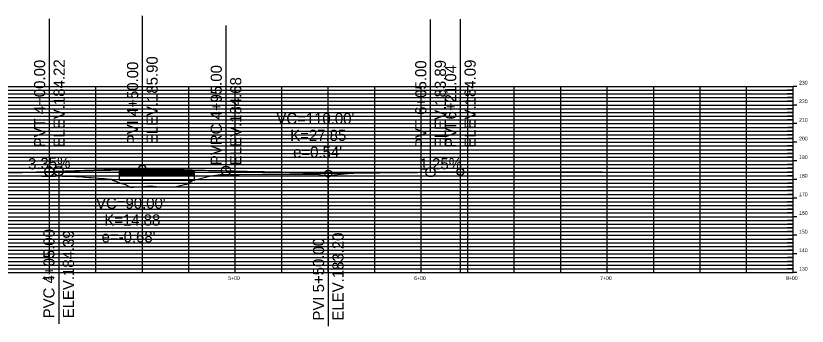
# Model space of a CAD drawing. Extents: x 1405440 to 1409538, y 1842123 to 1843178.
# Drawn here: x 1409112.2 to 1409537.8, y 1843011 to 1843177.7 of the extents above; entities that cross this region are included whole.
import ezdxf

# ---------------------------------------------------------------- set-up
doc = ezdxf.new("R2010")
doc.units = 0
for name, color, linetype in [('R_Axis_Annotation', 7, 'Continuous'), ('R_Exist Surface', 7, 'Continuous'), ('R_Grid Annot', 7, 'Continuous'), ('R_Grid_Minor', 7, 'Continuous'), ('R_SFHA', 7, 'Continuous'), ('R_Vert Alg', 7, 'Continuous'), ('R_Vert Alg Annot', 7, 'Continuous')]:
    doc.layers.add(name, color=color, linetype=linetype)

msp = doc.modelspace()

# ---------------------------------------------------------------- linework, layer by layer
for p, q in [((1408730.23, 1843139.81), (1409530.23, 1843139.81)), ((1408730.23, 1843139.81), (1409530.23, 1843139.81)), ((1409130.23, 1843039.81), (1409130.23, 1843139.81)), ((1409230.23, 1843039.81), (1409230.23, 1843139.81)), ((1409330.23, 1843039.81), (1409330.23, 1843139.81)), ((1409430.23, 1843039.81), (1409430.23, 1843139.81)), ((1409530.23, 1843039.81), (1409530.23, 1843139.81)), ((1408730.23, 1843129.81), (1409530.23, 1843129.81)), ((1408730.23, 1843119.81), (1409530.23, 1843119.81)), ((1408730.23, 1843109.81), (1409530.23, 1843109.81)), ((1408730.23, 1843099.81), (1409530.23, 1843099.81)), ((1408730.23, 1843089.81), (1409530.23, 1843089.81)), ((1408730.23, 1843079.81), (1409530.23, 1843079.81)), ((1408730.23, 1843069.81), (1409530.23, 1843069.81)), ((1408730.23, 1843059.81), (1409530.23, 1843059.81)), ((1408730.23, 1843049.81), (1409530.23, 1843049.81)), ((1408730.23, 1843039.81), (1409530.23, 1843039.81))]:
    msp.add_line(p, q)
at = {"layer": 'R_Exist Surface'}
msp.add_lwpolyline([(1409111.85, 1843091.83), (1409114.66, 1843091.79), (1409115.45, 1843091.79), (1409118.13, 1843091.79), (1409119.05, 1843091.77), (1409122.65, 1843091.69), (1409126.25, 1843091.6), (1409127.97, 1843091.55), (1409129.85, 1843091.57), (1409131.37, 1843091.59), (1409133.45, 1843091.63), (1409136.1, 1843091.69), (1409137.05, 1843091.66), (1409140.65, 1843091.53), (1409144.24, 1843091.38), (1409145.42, 1843091.32), (1409147.84, 1843091.15), (1409151.44, 1843090.89), (1409152.67, 1843090.79), (1409155.04, 1843090.63), (1409158.64, 1843090.36), (1409159.81, 1843090.27), (1409163.26, 1843089.98), (1409163.53, 1843089.95), (1409164.23, 1843089.35), (1409166.85, 1843088.47), (1409168.95, 1843087.72), (1409170.76, 1843087.29), (1409174.07, 1843085.42), (1409174.08, 1843085.42), (1409175.83, 1843085.66), (1409179.08, 1843085.83), (1409184.38, 1843086.36), (1409187.74, 1843086.06), (1409193.95, 1843085.83), (1409193.96, 1843085.83), (1409197.74, 1843085.9), (1409202.98, 1843087.13), (1409204.01, 1843087.28), (1409207.22, 1843089.28), (1409207.29, 1843089.3), (1409217.15, 1843091.7), (1409222.08, 1843092.46), (1409228.66, 1843092.53), (1409232.34, 1843092.52), (1409244.89, 1843092.6), (1409253.41, 1843092.58), (1409254.67, 1843092.59), (1409258.26, 1843092.61), (1409261.85, 1843092.63), (1409264.61, 1843092.66), (1409265.43, 1843092.66), (1409269.02, 1843092.67), (1409272.61, 1843092.68), (1409274.36, 1843092.69), (1409276.2, 1843092.39), (1409279.24, 1843091.92), (1409279.24, 1843091.92), (1409279.78, 1843091.96), (1409283.37, 1843092.28), (1409286.96, 1843092.61), (1409290.54, 1843092.95), (1409294.05, 1843093.29), (1409294.13, 1843093.29), (1409294.19, 1843093.29), (1409294.39, 1843093.3), (1409297.72, 1843093.36), (1409301.31, 1843093.43), (1409304.89, 1843093.5), (1409306.87, 1843093.54), (1409308.48, 1843093.56), (1409312.07, 1843093.58), (1409315.55, 1843093.61), (1409315.66, 1843093.61), (1409319.24, 1843093.64), (1409322.83, 1843093.67), (1409323.22, 1843093.67), (1409326.42, 1843093.7), (1409330.1, 1843093.74), (1409333.77, 1843093.78), (1409336.06, 1843093.8), (1409337.45, 1843093.81), (1409339.42, 1843093.83), (1409341.13, 1843093.84), (1409344.8, 1843093.87), (1409348.48, 1843093.89), (1409351.3, 1843093.91), (1409352.16, 1843093.91), (1409355.83, 1843093.91), (1409359.51, 1843093.91), (1409359.69, 1843093.91), (1409363.03, 1843093.91), (1409363.19, 1843093.91), (1409366.87, 1843093.91), (1409370.54, 1843093.9), (1409374.22, 1843093.9), (1409377.9, 1843093.89), (1409379.51, 1843093.89), (1409381.57, 1843093.89), (1409385.25, 1843093.89), (1409388.12, 1843093.89), (1409388.93, 1843093.89), (1409392.6, 1843093.88), (1409396.28, 1843093.88), (1409399.96, 1843093.87), (1409402.67, 1843093.87), (1409413.03, 1843093.86), (1409427.7, 1843093.83), (1409437.94, 1843093.82), (1409442.23, 1843093.83)], dxfattribs=at)
at = {"layer": 'R_Grid Annot'}
for p, q in [((1409532.23, 1843139.81), (1409530.23, 1843139.81)), ((1409532.23, 1843139.81), (1409530.23, 1843139.81)), ((1409530.23, 1843137.81), (1409527.23, 1843137.81)), ((1409530.23, 1843135.81), (1409527.23, 1843135.81)), ((1409530.23, 1843133.81), (1409527.23, 1843133.81)), ((1409530.23, 1843131.81), (1409527.23, 1843131.81)), ((1409530.23, 1843127.81), (1409527.23, 1843127.81)), ((1409530.23, 1843125.81), (1409527.23, 1843125.81)), ((1409532.23, 1843129.81), (1409530.23, 1843129.81)), ((1409530.23, 1843123.81), (1409527.23, 1843123.81)), ((1409530.23, 1843121.81), (1409527.23, 1843121.81)), ((1409530.23, 1843117.81), (1409527.23, 1843117.81)), ((1409532.23, 1843119.81), (1409530.23, 1843119.81)), ((1409530.23, 1843115.81), (1409527.23, 1843115.81)), ((1409530.23, 1843113.81), (1409527.23, 1843113.81)), ((1409530.23, 1843111.81), (1409527.23, 1843111.81)), ((1409532.23, 1843109.81), (1409530.23, 1843109.81)), ((1409530.23, 1843107.81), (1409527.23, 1843107.81)), ((1409530.23, 1843105.81), (1409527.23, 1843105.81)), ((1409530.23, 1843103.81), (1409527.23, 1843103.81)), ((1409530.23, 1843101.81), (1409527.23, 1843101.81)), ((1409530.23, 1843097.81), (1409527.23, 1843097.81)), ((1409532.23, 1843099.81), (1409530.23, 1843099.81)), ((1409530.23, 1843095.81), (1409527.23, 1843095.81)), ((1409530.23, 1843093.81), (1409527.23, 1843093.81)), ((1409530.23, 1843091.81), (1409527.23, 1843091.81)), ((1409530.23, 1843087.81), (1409527.23, 1843087.81)), ((1409532.23, 1843089.81), (1409530.23, 1843089.81)), ((1409530.23, 1843085.81), (1409527.23, 1843085.81)), ((1409530.23, 1843083.81), (1409527.23, 1843083.81)), ((1409530.23, 1843081.81), (1409527.23, 1843081.81)), ((1409532.23, 1843079.81), (1409530.23, 1843079.81)), ((1409530.23, 1843077.81), (1409527.23, 1843077.81)), ((1409530.23, 1843075.81), (1409527.23, 1843075.81)), ((1409530.23, 1843073.81), (1409527.23, 1843073.81)), ((1409530.23, 1843071.81), (1409527.23, 1843071.81)), ((1409530.23, 1843067.81), (1409527.23, 1843067.81)), ((1409532.23, 1843069.81), (1409530.23, 1843069.81)), ((1409530.23, 1843065.81), (1409527.23, 1843065.81)), ((1409530.23, 1843063.81), (1409527.23, 1843063.81)), ((1409530.23, 1843061.81), (1409527.23, 1843061.81)), ((1409530.23, 1843057.81), (1409527.23, 1843057.81)), ((1409532.23, 1843059.81), (1409530.23, 1843059.81)), ((1409530.23, 1843055.81), (1409527.23, 1843055.81)), ((1409530.23, 1843053.81), (1409527.23, 1843053.81)), ((1409530.23, 1843051.81), (1409527.23, 1843051.81)), ((1409532.23, 1843049.81), (1409530.23, 1843049.81)), ((1409530.23, 1843047.81), (1409527.23, 1843047.81)), ((1409530.23, 1843045.81), (1409527.23, 1843045.81)), ((1409530.23, 1843043.81), (1409527.23, 1843043.81)), ((1409530.23, 1843041.81), (1409527.23, 1843041.81)), ((1409532.23, 1843039.81), (1409530.23, 1843039.81))]:
    msp.add_line(p, q, dxfattribs=at)
at = {"layer": 'R_Grid_Minor'}
for p, q in [((1409155.23, 1843039.81), (1409155.23, 1843139.81)), ((1409180.23, 1843039.81), (1409180.23, 1843139.81)), ((1409205.23, 1843039.81), (1409205.23, 1843139.81)), ((1409255.23, 1843039.81), (1409255.23, 1843139.81)), ((1409280.23, 1843039.81), (1409280.23, 1843139.81)), ((1409305.23, 1843039.81), (1409305.23, 1843139.81)), ((1409355.23, 1843039.81), (1409355.23, 1843139.81)), ((1409380.23, 1843039.81), (1409380.23, 1843139.81)), ((1409405.23, 1843039.81), (1409405.23, 1843139.81)), ((1409455.23, 1843039.81), (1409455.23, 1843139.81)), ((1409480.23, 1843039.81), (1409480.23, 1843139.81)), ((1409505.23, 1843039.81), (1409505.23, 1843139.81)), ((1408730.23, 1843137.81), (1409530.23, 1843137.81)), ((1408730.23, 1843135.81), (1409530.23, 1843135.81)), ((1408730.23, 1843133.81), (1409530.23, 1843133.81)), ((1408730.23, 1843131.81), (1409530.23, 1843131.81)), ((1408730.23, 1843127.81), (1409530.23, 1843127.81)), ((1408730.23, 1843125.81), (1409530.23, 1843125.81)), ((1408730.23, 1843123.81), (1409530.23, 1843123.81)), ((1408730.23, 1843121.81), (1409530.23, 1843121.81)), ((1408730.23, 1843117.81), (1409530.23, 1843117.81)), ((1408730.23, 1843115.81), (1409530.23, 1843115.81)), ((1408730.23, 1843113.81), (1409530.23, 1843113.81)), ((1408730.23, 1843111.81), (1409530.23, 1843111.81)), ((1408730.23, 1843107.81), (1409530.23, 1843107.81)), ((1408730.23, 1843105.81), (1409530.23, 1843105.81)), ((1408730.23, 1843103.81), (1409530.23, 1843103.81)), ((1408730.23, 1843101.81), (1409530.23, 1843101.81)), ((1408730.23, 1843097.81), (1409530.23, 1843097.81)), ((1408730.23, 1843095.81), (1409530.23, 1843095.81)), ((1408730.23, 1843093.81), (1409530.23, 1843093.81)), ((1408730.23, 1843091.81), (1409530.23, 1843091.81)), ((1408730.23, 1843087.81), (1409530.23, 1843087.81)), ((1408730.23, 1843085.81), (1409530.23, 1843085.81)), ((1408730.23, 1843083.81), (1409530.23, 1843083.81)), ((1408730.23, 1843081.81), (1409530.23, 1843081.81)), ((1408730.23, 1843077.81), (1409530.23, 1843077.81)), ((1408730.23, 1843075.81), (1409530.23, 1843075.81)), ((1408730.23, 1843073.81), (1409530.23, 1843073.81)), ((1408730.23, 1843071.81), (1409530.23, 1843071.81)), ((1408730.23, 1843067.81), (1409530.23, 1843067.81)), ((1408730.23, 1843065.81), (1409530.23, 1843065.81)), ((1408730.23, 1843063.81), (1409530.23, 1843063.81)), ((1408730.23, 1843061.81), (1409530.23, 1843061.81)), ((1408730.23, 1843057.81), (1409530.23, 1843057.81)), ((1408730.23, 1843055.81), (1409530.23, 1843055.81)), ((1408730.23, 1843053.81), (1409530.23, 1843053.81)), ((1408730.23, 1843051.81), (1409530.23, 1843051.81)), ((1408730.23, 1843047.81), (1409530.23, 1843047.81)), ((1408730.23, 1843045.81), (1409530.23, 1843045.81)), ((1408730.23, 1843043.81), (1409530.23, 1843043.81)), ((1408730.23, 1843041.81), (1409530.23, 1843041.81))]:
    msp.add_line(p, q, dxfattribs=at)
at = {"layer": 'R_SFHA'}
for p, q in [((1409351.27, 1843039.81), (1409351.27, 1843139.81)), ((1409180.23, 1843095.71), (1409080.23, 1843092.36)), ((1409167.88, 1843089.44), (1409167.88, 1843094.36)), ((1409167.88, 1843094.36), (1409208.21, 1843094.36)), ((1409167.88, 1843093.28), (1409208.21, 1843093.28)), ((1409167.88, 1843092.44), (1409208.21, 1843092.44)), ((1409180.23, 1843095.71), (1409280.23, 1843093.01)), ((1409208.21, 1843089.44), (1409208.21, 1843094.36)), ((1409351.27, 1843093.9), (1409280.23, 1843093.01)), ((1409167.88, 1843089.44), (1409208.21, 1843089.44))]:
    msp.add_line(p, q, dxfattribs=at)
at = {"layer": 'R_Vert Alg'}
for p, q in [((1409130.23, 1843094.04), (1409135.23, 1843094.21)), ((1409335.23, 1843093.7), (1409351.27, 1843093.9))]:
    msp.add_line(p, q, dxfattribs=at)
for points in [[(1409111.48, 1843093.48), (1409113.57, 1843093.53), (1409115.65, 1843093.59), (1409117.73, 1843093.65), (1409119.82, 1843093.71), (1409121.9, 1843093.77), (1409123.98, 1843093.84), (1409126.07, 1843093.9), (1409128.15, 1843093.97), (1409130.23, 1843094.04)], [(1409135.23, 1843094.21), (1409137.11, 1843094.27), (1409138.98, 1843094.33), (1409140.86, 1843094.38), (1409142.73, 1843094.44), (1409144.61, 1843094.49), (1409146.48, 1843094.54), (1409148.36, 1843094.59), (1409150.23, 1843094.63), (1409152.11, 1843094.67), (1409153.98, 1843094.72), (1409155.86, 1843094.75), (1409157.73, 1843094.79), (1409159.61, 1843094.82), (1409161.48, 1843094.85), (1409163.36, 1843094.88), (1409165.23, 1843094.91), (1409167.11, 1843094.93), (1409168.98, 1843094.95), (1409170.86, 1843094.97), (1409172.73, 1843094.99), (1409174.61, 1843095), (1409176.48, 1843095.02), (1409178.36, 1843095.02), (1409182.11, 1843095.04), (1409183.98, 1843095.04), (1409185.86, 1843095.04), (1409187.73, 1843095.04), (1409189.61, 1843095.03), (1409191.48, 1843095.03), (1409193.36, 1843095.02), (1409195.23, 1843095.01), (1409197.11, 1843094.99), (1409198.98, 1843094.97), (1409200.86, 1843094.96), (1409202.73, 1843094.94), (1409204.61, 1843094.91), (1409206.48, 1843094.89), (1409208.36, 1843094.86), (1409210.23, 1843094.83), (1409212.11, 1843094.79), (1409213.98, 1843094.76), (1409215.86, 1843094.72), (1409217.73, 1843094.68), (1409219.61, 1843094.64), (1409221.48, 1843094.59), (1409223.36, 1843094.55), (1409225.23, 1843094.5)], [(1409225.23, 1843094.5), (1409227.52, 1843094.44), (1409229.82, 1843094.38), (1409232.11, 1843094.32), (1409234.4, 1843094.27), (1409236.69, 1843094.21), (1409238.98, 1843094.16), (1409241.27, 1843094.11), (1409243.57, 1843094.06), (1409245.86, 1843094.02), (1409248.15, 1843093.97), (1409250.44, 1843093.93), (1409252.73, 1843093.89), (1409255.02, 1843093.85), (1409257.32, 1843093.82), (1409259.61, 1843093.78), (1409261.9, 1843093.75), (1409264.19, 1843093.72), (1409266.48, 1843093.69), (1409268.77, 1843093.66), (1409271.07, 1843093.64), (1409273.36, 1843093.61), (1409275.65, 1843093.59), (1409277.94, 1843093.57), (1409282.52, 1843093.54), (1409284.82, 1843093.53), (1409287.11, 1843093.51), (1409289.4, 1843093.5), (1409291.69, 1843093.5), (1409293.98, 1843093.49), (1409296.27, 1843093.49), (1409298.57, 1843093.48), (1409300.86, 1843093.48), (1409303.15, 1843093.48), (1409305.44, 1843093.49), (1409307.73, 1843093.49), (1409310.02, 1843093.5), (1409312.32, 1843093.51), (1409314.61, 1843093.52), (1409316.9, 1843093.53), (1409319.19, 1843093.55), (1409321.48, 1843093.56), (1409323.77, 1843093.58), (1409326.07, 1843093.6), (1409328.36, 1843093.62), (1409330.65, 1843093.65), (1409332.94, 1843093.67), (1409335.23, 1843093.7)]]:
    msp.add_lwpolyline(points, dxfattribs=at)
at = {"layer": 'R_Vert Alg Annot'}
for p, q in [((1409180.23, 1843105.71), (1409180.23, 1843177.71)), ((1409130.23, 1843104.04), (1409130.23, 1843176.04)), ((1409335.23, 1843103.7), (1409335.23, 1843175.7)), ((1409351.27, 1843103.9), (1409351.27, 1843175.9)), ((1409225.23, 1843094.5), (1409225.23, 1843172.5)), ((1409180.23, 1843095.71), (1409180.23, 1843105.71)), ((1409130.23, 1843094.04), (1409130.23, 1843104.04)), ((1409335.23, 1843093.7), (1409335.23, 1843103.7)), ((1409351.27, 1843093.9), (1409351.27, 1843103.9)), ((1409135.23, 1843094.21), (1409135.23, 1843084.21)), ((1409157.73, 1843094.96), (1409180.23, 1843095.71)), ((1409180.23, 1843095.71), (1409202.73, 1843095.11)), ((1409252.73, 1843093.76), (1409280.23, 1843093.01)), ((1409280.23, 1843093.01), (1409307.73, 1843093.36)), ((1409280.23, 1843093.01), (1409280.23, 1843083.01)), ((1409135.23, 1843084.21), (1409135.23, 1843012.21)), ((1409280.23, 1843083.01), (1409280.23, 1843011.01))]:
    msp.add_line(p, q, dxfattribs=at)
for centre, radius in [((1409130.23, 1843094.04), 2.5), ((1409135.23, 1843094.21), 2.5), ((1409180.23, 1843095.71), 1.85), ((1409225.23, 1843094.5), 2.5), ((1409335.23, 1843093.7), 2.5), ((1409280.23, 1843093.01), 1.85), ((1409351.27, 1843093.9), 1.85)]:
    msp.add_circle(centre, radius, dxfattribs=at)

# ---------------------------------------------------------------- texts
at = {"layer": 'R_Axis_Annotation'}
for s, p in [('230', (1409533.43, 1843140.81)), ('230', (1409533.43, 1843140.81)), ('220', (1409533.43, 1843130.81)), ('210', (1409533.43, 1843120.81)), ('200', (1409533.43, 1843110.81)), ('190', (1409533.43, 1843100.81)), ('180', (1409533.43, 1843090.81)), ('170', (1409533.43, 1843080.81)), ('160', (1409533.43, 1843070.81)), ('150', (1409533.43, 1843060.81)), ('140', (1409533.43, 1843050.81)), ('130', (1409533.43, 1843040.81)), ('4+00', (1409126.43, 1843035.81)), ('5+00', (1409226.43, 1843035.81)), ('6+00', (1409326.43, 1843035.81)), ('7+00', (1409426.43, 1843035.81)), ('8+00', (1409526.43, 1843035.81))]:
    msp.add_text(s, height=2, dxfattribs=at).set_placement(p)
at = {"layer": 'R_Vert Alg Annot'}
for s, rotation, p in [('ELEV.185.90', 90, (1409188.48, 1843108.71)), ('PVT 4+00.00', 90, (1409127.98, 1843107.04)), ('ELEV.184.22', 90, (1409138.48, 1843107.04)), ('PVI 4+50.00', 90, (1409177.98, 1843108.71)), ('PVT 6+05.00', 90, (1409332.98, 1843106.7)), ('ELEV.183.89', 90, (1409343.48, 1843106.7)), ('ELEV.184.09', 90, (1409359.52, 1843106.9)), ('PVRC 4+95.00', 90, (1409222.98, 1843097.5)), ('PVI 6+21.04', 90, (1409349.02, 1843106.9)), ('ELEV.184.68', 90, (1409233.48, 1843097.5)), ('3.35%', 1.9187, (1409118.89, 1843095.16)), ('1.25%', 0.7162, (1409329.44, 1843095.13)), ('PVC 4+05.00', 90, (1409132.98, 1843015.21)), ('ELEV.184.39', 90, (1409143.48, 1843015.21)), ('PVI 5+50.00', 90, (1409277.98, 1843014.01)), ('ELEV.183.20', 90, (1409288.48, 1843014.01))]:
    msp.add_text(s, height=6, rotation=rotation, dxfattribs=at).set_placement(p)
for s, p in [("VC=110.00'", (1409252.33, 1843119.54)), ('K=27.85', (1409259.77, 1843110.54)), ("e=0.54'", (1409261.33, 1843101.54)), ("VC=90.00'", (1409155.33, 1843074.04)), ('K=14.88', (1409159.76, 1843065.04)), ("e=-0.68'", (1409158.33, 1843056.04))]:
    msp.add_text(s, height=6, dxfattribs=at).set_placement(p)

doc.saveas('drawing.dxf')
